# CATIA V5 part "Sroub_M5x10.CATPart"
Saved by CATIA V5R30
Part number: Sroub_M5x10
Definition: E 1220_5x10_3
Nomenclature: E 1220_5x10_3
Source: Unknown
Description: PART--DESC
Bounding box of the stored display mesh (mm): x 199 to 209, y -94.99 to -85.01, z -223.5 to -213.5
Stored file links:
  E:\Bakalarka\Model\Forma_v7\Sroub_M5x10.CATPart
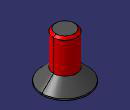
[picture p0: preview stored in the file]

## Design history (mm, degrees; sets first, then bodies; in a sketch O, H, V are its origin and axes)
Body1 "MANIFOLD_SOLID_BREP #4026" (main body)
  Solid1: solid without history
